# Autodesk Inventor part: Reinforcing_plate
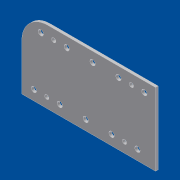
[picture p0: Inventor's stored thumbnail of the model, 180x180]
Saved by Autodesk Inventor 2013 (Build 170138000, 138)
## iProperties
Shininess: 69.0
Length Units: 11269
Angle Units: 11279
Time Units: 11290
Mass Units: 11283
Length Display Precision: 3
Angle Display Precision: 2
Created: 2001-04
Part Number: Reinforcing_plate
Material: Standard
Document SubType Name: Modellieren
Designer: dl
Density: 1 g/cm^3
Density: 0.0
Volumn: 0.0
Area: 0.0
PropertySet Name: Model Information
Control State: 0
Master: False
Checked Out: False
Author: dl
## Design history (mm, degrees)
body "Solid1"
sketch "Sketch1"
  geometry: L1 (1.035, 20.585)-(156.035, 20.585); L2 (156.035, 20.585)-(156.035, -63.415); L3 (156.035, -63.415)-(1.035, -63.415); L4 (1.035, -63.415)-(1.035, 20.585)
  constraints: 8 end point, 2 parallel, 1 horizontal, 1 perpendicular
  dimensions: "d0" = 155 distance of L1.start L1.end; "d1" = 84 distance of L3.end L1.start
extrude "Extrusion1" new body sketch "Sketch1" distance "d2" = 3; taper "d3" = 0 deg
sketch "Sketch2"
  geometry: L1 (1.035, -63.415)-(1.035, 20.585) reference; L2 (156.035, -63.415)-(1.035, -63.415) reference; 2 further points
  dimensions: "d4" = 11.5 distance from line of L2 point (15.035, -51.915); "d5" = 14 distance from line of point (15.035, -51.915) L1; "d6" = 61 vertical distance of point (15.035, -51.915) point (23.035, 9.085); "d7" = 8 horizontal distance of point (15.035, -51.915) point (23.035, 9.085)
sketch "Sketch3"
  geometry: C1 r 3.1 at (45.035, -51.915) reference; C2 r 3.1 at (135.035, -51.915) reference; C3 r 3.1 at (143.035, 9.085) reference; C4 r 3.1 at (15.035, -51.915) reference; C5 r 3.1 at (23.035, 9.085) reference; 4 further points
  dimensions: "d18" = 15 distance of C5.centre point (38.035, 9.085); "d19" = 15 distance of C3.centre point (128.035, 9.085) (= d18); "d20" = 0 vertical distance of C2.centre point (120.035, -51.915); "d21" = 15 distance of C2.centre point (120.035, -51.915) (= d18); "d22" = 15 distance of C1.centre point (30.035, -51.915) (= d18); "d23" = 0 vertical distance of C4.centre point (30.035, -51.915); "d24" = 61 vertical distance of point (30.035, -51.915) point (38.035, 9.085); "d25" = 61 vertical distance of point (120.035, -51.915) point (128.035, 9.085)
hole "Hole1" sketch "Sketch2" diameter "d8" = 6.2; stored, may be unused: countersink angle "d12" = 60 deg, drill point angle "d14" = 118 deg; dims "d9" = 6, "d10" = 4, "d11" = 2, "d13" = 8
pattern_linear "Rectangular Pattern1" dims "d17" = 30
hole "Hole2" sketch "Sketch3" diameter "d26" = 5; stored, may be unused: countersink angle "d30" = 60 deg, drill point angle "d32" = 118 deg; dims "d27" = 6, "d28" = 4, "d29" = 2, "d31" = 8
fillet "Fillet1" dims "d34" = 30
